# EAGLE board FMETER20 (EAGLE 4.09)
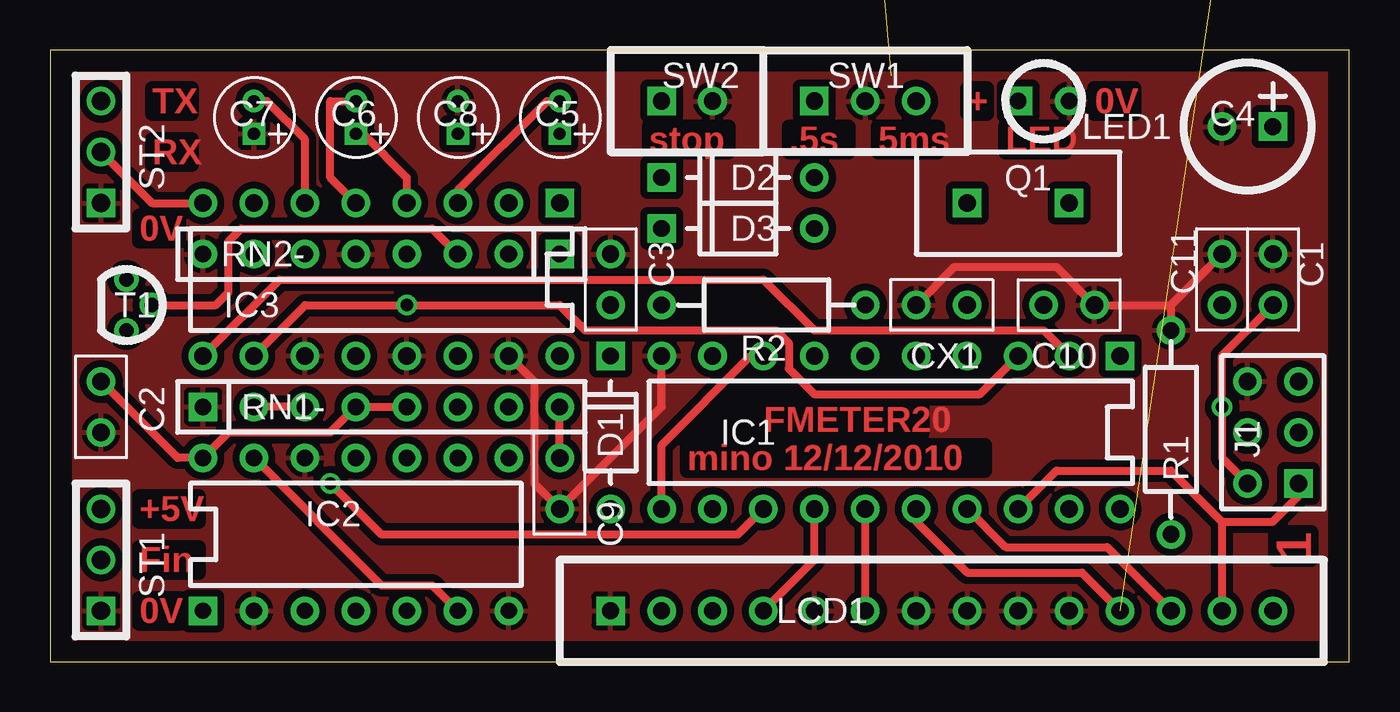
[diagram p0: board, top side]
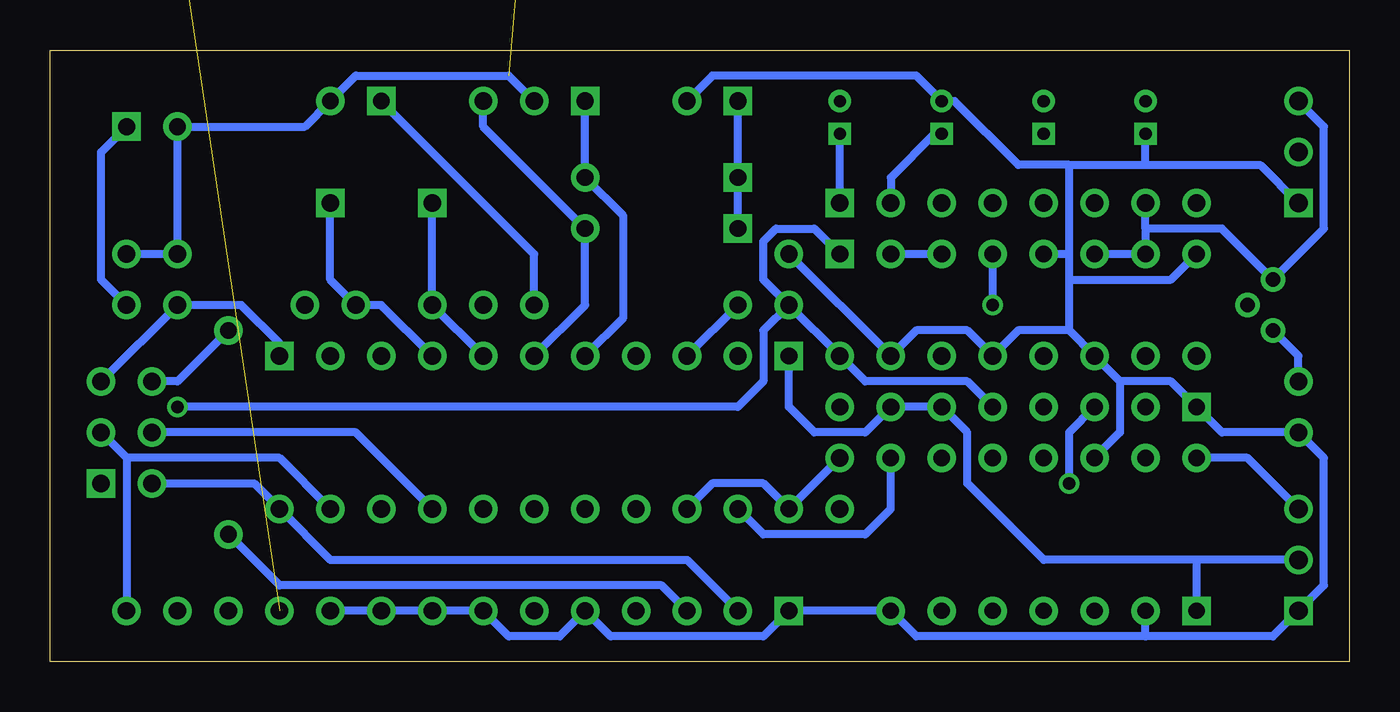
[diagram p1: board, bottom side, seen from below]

Size 64.77 x 30.48 mm. Coordinates in mm from the lower left corner, seen from the top.
Outline: 0,0 64.77,0 64.77,30.48 0,30.48 0,0
Copper layers used: Top, Bottom

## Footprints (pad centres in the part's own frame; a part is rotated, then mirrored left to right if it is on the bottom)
02P100QA = drill 0.864 pad 1.422 round: 1 0,0; 2 2.54,0
02P100RA = drill 0.838 pad 1.422 round: N 0,0 | drill 0.838 pad 1.422 square: P 2.54,0
ELK_MINI = drill 0.61 pad 1.016 round: N 0,0 | drill 0.61 pad 1.016 square: P 1.626,0
02P300IV = drill 0.838 pad 1.422 round: A 0,0 | drill 0.838 pad 1.422 square: K 7.62,0
DIL20 = drill 0.864 pad 1.422 square: 1 0,0 | drill 0.864 pad 1.422 round: 2 2.54,0; 3 5.08,0; 4 7.62,0; 5 10.16,0; 6 12.7,0; 7 15.24,0; 8 17.78,0; 9 20.32,0; 10 22.86,0; 11 22.86,7.62; 12 20.32,7.62; 13 17.78,7.62; 14 15.24,7.62; 15 12.7,7.62; 16 10.16,7.62; 17 7.62,7.62; 18 5.08,7.62; 19 2.54,7.62; 20 0,7.62
DIL14 = drill 0.813 pad 1.422 square: 1 0,0 | drill 0.813 pad 1.422 round: 2 2.54,0; 3 5.08,0; 4 7.62,0; 5 10.16,0; 6 12.7,0; 7 15.24,0; 8 15.24,7.62; 9 12.7,7.62; 10 10.16,7.62; 11 7.62,7.62; 12 5.08,7.62; 13 2.54,7.62; 14 0,7.62
DIL16 = drill 0.864 pad 1.422 square: 1 0,0 | drill 0.864 pad 1.422 round: 2 2.54,0; 3 5.08,0; 4 7.62,0; 5 10.16,0; 6 12.7,0; 7 15.24,0; 8 17.78,0; 9 17.78,7.62; 10 15.24,7.62; 11 12.7,7.62; 12 10.16,7.62; 13 7.62,7.62; 14 5.08,7.62; 15 2.54,7.62; 16 0,7.62
CON03X2 = drill 0.864 pad 1.422 square: 1 0,0 | drill 0.864 pad 1.422 round: 2 0,2.54; 3 2.54,0; 4 2.54,2.54; 5 5.08,0; 6 5.08,2.54
14X1 = drill 0.864 pad 1.422 square: 1 0,0 | drill 0.864 pad 1.422 round: 2 2.54,0; 3 5.08,0; 4 7.62,0; 5 10.16,0; 6 12.7,0; 7 15.24,0; 8 17.78,0; 9 20.32,0; 10 22.86,0; 11 25.4,0; 12 27.94,0; 13 30.48,0; 14 33.02,0
LED3 = drill 0.813 pad 1.422 square: + 0,0 | drill 0.813 pad 1.422 round: - 2.54,0
QS = drill 0.864 pad 1.422 square: 1 2.54,2.54; 2 7.62,2.54
02P400IL = drill 0.838 pad 1.422 round: 1 0,0; 2 10.16,0
08P100QA = drill 0.838 pad 1.422 square: 1 0,0 | drill 0.838 pad 1.422 round: 2 2.54,0; 3 5.08,0; 4 7.62,0; 5 10.16,0; 6 12.7,0; 7 15.24,0; 8 17.78,0
3X1 = drill 0.914 pad 1.422 square: 1 0,0 | drill 0.914 pad 1.422 round: 2 2.54,0; 3 5.08,0
SW-1UM = drill 0.864 pad 1.422 square: 1 0,0 | drill 0.864 pad 1.422 round: 2 2.54,0; 3 5.08,0
SW-1EIN = drill 0.864 pad 1.422 square: 1 0,0 | drill 0.864 pad 1.422 round: 2 2.54,0
TO92 = drill 0.711 pad 1.118 round: 1 0,2.54; 2 1.27,1.27; 3 0,0

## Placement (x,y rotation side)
C1  .1uF  [02P100QA]  60.96,20.32 270 top
C2  .1uF  [02P100QA]  2.54,11.43 90 top
C3  .1uF  [02P100QA]  27.94,20.32 270 top
C4  100uF  [02P100RA]  58.42,26.67 0 top
C5  10uF  [ELK_MINI]  25.4,27.94 270 top
C6  10uF  [ELK_MINI]  15.24,27.94 270 top
C7  10uF  [ELK_MINI]  10.16,27.94 270 top
C8  10uF  [ELK_MINI]  20.32,27.94 270 top
C9  100p  [02P100QA]  25.4,7.62 90 top
C10  18p  [02P100QA]  49.53,17.78 0 top
C11  .1uF  [02P100QA]  58.42,20.32 270 top
CX1  18p  [02P100QA]  45.72,17.78 180 top
D1  1N914  [02P300IV]  27.94,7.62 90 top
D2  1N914  [02P300IV]  38.1,24.13 180 top
D3  1N914  [02P300IV]  38.1,21.59 180 top
IC1  ATtiny2313P  [DIL20]  53.34,15.24 180 top
IC2  74HC393  [DIL14]  7.62,2.54 0 top
IC3  MAX232  [DIL16]  25.4,22.86 180 top
J1  Progr.  [CON03X2]  62.23,8.89 90 top
LCD1  LM16X21  [14X1]  27.94,2.54 0 top
LED1  LED3MM  [LED3]  48.26,27.94 0 top
Q1  20MHz  [QS]  43.18,20.32 0 top
R1  1k  [02P400IL]  55.88,16.51 270 top
R2  2k2  [02P400IL]  40.64,17.78 180 top
R3  4k7  [02P400IL]  not placed on the board
RN1-  22k  [08P100QA]  7.62,12.7 0 top
RN2-  4k7  [08P100QA]  25.4,20.32 180 top
ST1  Eingang  [3X1]  2.54,2.54 90 top
ST2  V.24  [3X1]  2.54,22.86 90 top
SW1  1xUM  [SW-1UM]  38.1,27.94 0 top
SW2  1xEIN  [SW-1EIN]  30.48,27.94 0 top
SW3  f*128  [SW-1EIN]  not placed on the board
T1  BC327  [TO92]  3.81,16.51 0 top

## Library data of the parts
C1-C4 C9-C11 CX1 D1-D3 R1-R3 RN1- RN2- = DISCRETE
C5-C8 = DISCRETE@2
IC1 Q1 SW1-SW3 = MINO
IC2 = M745XX
IC3 = MINO@2
J1 ST1 ST2 = CONNEC
LCD1 = LCD
LED1 T1 = ANALOG

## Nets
1SEK.: D2.A IC1.7 SW1.1
10MS: D3.A IC1.6 SW1.3
C6: C6.N IC3.5
FEXTERN: CX1.1 IC1.5 Q1.1
FIN: D1.K IC2.1 RN1-.6 RN1-.7 ST1.2
GND: C1.1 C2.1 C3.1 C4.N C7.P C8.N C9.1 C10.2 C11.1 CX1.2 IC1.10 IC2.2 IC2.7 IC2.12 IC3.11 IC3.13 IC3.15 J1.6 LCD1.1 LCD1.5 LCD1.7 LCD1.8 LCD1.9 LCD1.10 LED1.- R1.1 RN1-.1 RN2-.5 RN2-.8 ST1.1 ST2.1 SW1.2 SW2.2 SW3.1
HALT: D2.K D3.K SW2.1
MISO: IC1.18 J1.1 LCD1.13
MOSI: IC1.17 J1.4 LCD1.12
N$1: R3.1 SW3.2
N$2: IC1.2 IC3.9
N$3: IC1.3 IC3.10 RN2-.4
N$4: IC1.16 LCD1.11 R3.2
N$5: IC2.6 IC2.13
N$6: IC1.15 LCD1.6
N$7: C5.P IC3.1
N$8: C6.P IC3.4
N$9: C7.N IC3.6
N$10: C8.P IC3.2
N$11: C5.N IC3.3
N$13: IC1.14 LCD1.4
N$14: RN2-.2 RN2-.3 T1.2
N$16: C10.1 IC1.4 Q1.2
N$17: IC1.8 IC1.11 IC2.8
N$19: IC1.13 RN1-.2 RN1-.3
N$20: C9.2 D1.A IC1.12 RN1-.8
N$24: LCD1.3 R1.2
N$25: IC1.9 R2.2
N$26: LED1.+ R2.1
RESET: C11.2 IC1.1 J1.5
RXD: IC3.8 ST2.2
SCLK: IC1.19 J1.3 LCD1.14
TXD: IC3.7 RN2-.6 RN2-.7 ST2.3 T1.1
VCC: C1.2 C2.2 C3.2 C4.P IC1.20 IC2.14 IC3.16 J1.2 LCD1.2 RN1-.4 RN1-.5 RN2-.1 ST1.3 T1.3

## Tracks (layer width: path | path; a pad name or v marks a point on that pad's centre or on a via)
1SEK.
  Bottom 0.406: IC1.7 36.2,17.14 36.2,22.23 D2.A SW1.1
10MS
  Bottom 0.406: IC1.6 38.1,17.78 D3.A 43.18,26.67 SW1.3
C6
  Top 0.406: C6.N 13.97,27.94 13.97,24.13 IC3.5
FEXTERN
  Bottom 0.406: IC1.5 CX1.1 Q1.1
FIN
  Bottom 0.406: D1.K 27.94,12.7 26.67,11.43 24.13,11.43 RN1-.7 RN1-.6 19.05,11.43 19.05,8.89 15.24,5.08 7.62,5.08 | 7.62,5.08 IC2.1 | ST1.2 7.62,5.08
GND  (1 unrouted)
  Top 0.406: CX1.2 45.09,19.68 50.16,19.68 C10.2 55.88,17.78 | 55.88,17.78 C11.1 | IC3.15 24.13,13.97 24.13,8.89 C9.1 30.48,12.7 IC1.10 | 55.88,17.78 R1.1
  Bottom 0.406: C1.1 C11.1 C4.N 52.07,26.67 LED1.- 49.53,29.21 41.91,29.21 SW1.2 | J1.6 58.42,13.97 R1.1 | 13.97,16.51 IC3.11 11.43,13.97 | ST2.1 4.45,24.77 10.16,24.77 | 13.97,24.77 10.16,24.77 | 13.97,24.77 16.51,24.77 19.68,27.94 C8.N 21.59,29.21 31.75,29.21 SW2.2 | 11.43,13.97 8.89,13.97 RN1-.1 6.35,11.43 C2.1 1.27,10.16 1.27,3.81 ST1.1 3.81,1.27 10.16,1.27 | IC2.12 11.43,11.43 11.43,13.97 | C3.1 IC3.15 21.59,16.51 19.05,16.51 IC3.13 16.51,16.51 13.97,16.51 | 13.97,16.51 13.97,19.05 | 13.97,19.05 13.97,20.32 | 13.97,20.32 13.97,24.77 | 10.16,24.77 C7.P | 13.97,20.32 RN2-.5 | RN2-.8 8.89,19.05 13.97,19.05 | 10.16,1.27 21.59,1.27 IC2.7 LCD1.1 29.21,1.27 36.83,1.27 LCD1.5 39.37,1.27 41.91,1.27 LCD1.7 LCD1.8 LCD1.9 LCD1.10 | 10.16,1.27 IC2.2
  pour Top (isolate 0.356): 64.14,29.84 0.64,29.84 0.64,0.64 64.14,0.64
HALT
  Bottom 0.406: D3.K D2.K SW2.1
MISO
  Top 0.406: J1.1 62.23,8.26 60.96,6.99 58.42,6.99 | 58.42,6.99 55.88,9.53 50.16,9.53 IC1.18 | 58.42,6.99 LCD1.13
MOSI
  Top 0.406: IC1.17 47.62,5.71 52.7,5.71 LCD1.12
  Bottom 0.406: J1.4 49.53,11.43 IC1.17
N$1  (1 unrouted)
N$2
  Top 0.406: IC3.9 11.43,19.05 35.56,19.05 38.1,16.51 49.53,16.51 IC1.2
N$3  (via drill 0.61 pad 1.02)
  Top 0.406: IC3.10 12.7,17.78 v17.78,17.78 25.4,17.78 26.67,16.51 36.2,16.51 36.83,15.88 36.83,14.61 38.1,13.34 46.35,13.34 IC1.3
  Bottom 0.406: v17.78,17.78 RN2-.4
N$4  (1 unrouted)
  Top 0.406: IC1.16 43.18,6.99 45.72,4.45 51.44,4.45 LCD1.11
N$5
  Top 0.406: IC2.13 16.51,3.81 19.05,3.81 IC2.6
N$6
  Top 0.406: LCD1.6 IC1.15
N$7
  Bottom 0.406: IC3.1 C5.P
N$8
  Top 0.406: C6.P 15.6,26.31 17.78,24.13 IC3.4
N$9
  Top 0.406: C7.N 10.79,27.94 12.7,26.04 IC3.6
N$10
  Bottom 0.406: C8.P 20.68,26.31 22.86,24.13 IC3.2
N$11
  Top 0.406: IC3.3 20.32,23.5 24.77,27.94 C5.N
N$13
  Top 0.406: IC1.14 38.1,5.08 LCD1.4
N$14
  Top 0.406: RN2-.3 19.05,21.59 9.53,21.59 8.89,20.95 8.89,18.41 8.26,17.78 T1.2
  Bottom 0.406: RN2-.3 RN2-.2
N$16
  Bottom 0.406: IC1.4 48.26,17.78 C10.1 50.8,19.05 Q1.2
N$17
  Top 0.406: IC1.11 30.48,10.79 34.92,15.24 IC1.8
  Bottom 0.406: IC2.8 22.86,7.62 24.13,6.35 29.21,6.35 IC1.11
N$19  (via drill 0.61 pad 1.02)
  Top 0.406: RN1-.3 RN1-.2 | v13.97,8.89 16.51,6.35 34.29,6.35 IC1.13
  Bottom 0.406: RN1-.3 13.97,11.43 v13.97,8.89
N$20
  Top 0.406: C9.2 RN1-.8
  Bottom 0.406: C9.2 D1.A 29.21,8.89 31.75,8.89 IC1.12
N$24
  Bottom 0.406: LCD1.3 34.29,3.81 53.34,3.81 R1.2
N$25
  Bottom 0.406: R2.2 IC1.9
N$26
  Bottom 0.406: LED1.+ 40.64,20.32 R2.1
RESET
  Bottom 0.406: J1.5 C11.2 55.24,17.78 53.34,15.88 IC1.1
RXD
  Top 0.406: ST2.2 5.08,22.86 IC3.8
SCLK
  Bottom 0.406: 60.96,10.16 53.34,10.16 IC1.19 | 60.96,10.16 J1.3 | 60.96,10.16 LCD1.14
TXD
  Bottom 0.406: RN2-.6 RN2-.7 10.16,21.59 | ST2.3 1.27,26.67 1.27,21.59 T1.1 6.35,21.59 10.16,21.59 | 10.16,21.59 IC3.7
VCC  (via drill 0.61 pad 1.02)
  Top 0.406: RN1-.5 RN1-.4 13.97,11.43 8.89,11.43 IC2.14 6.35,10.16 C2.2 | C1.2 58.42,15.24 v58.42,12.7 58.42,10.16 J1.2
  Bottom 0.406: C1.2 62.23,19.05 62.23,25.4 C4.P | ST1.3 5.08,10.16 IC2.14 | RN1-.5 19.05,13.97 24.13,13.97 IC3.16 C3.2 | J1.2 54.61,8.89 IC1.20 50.8,5.08 33.02,5.08 LCD1.2 | v58.42,12.7 30.48,12.7 29.21,13.97 29.21,16.51 C3.2 | RN2-.1 26.67,21.59 28.57,21.59 29.21,20.95 29.21,19.05 C3.2 | C2.2 2.54,15.24 T1.3

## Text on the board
Top: TX | + | 0V | RX | stop | .5s | 5ms | LED | 0V | FMETER20 | mino 12/12/2010 | +5V | 1 | Fin | 0V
